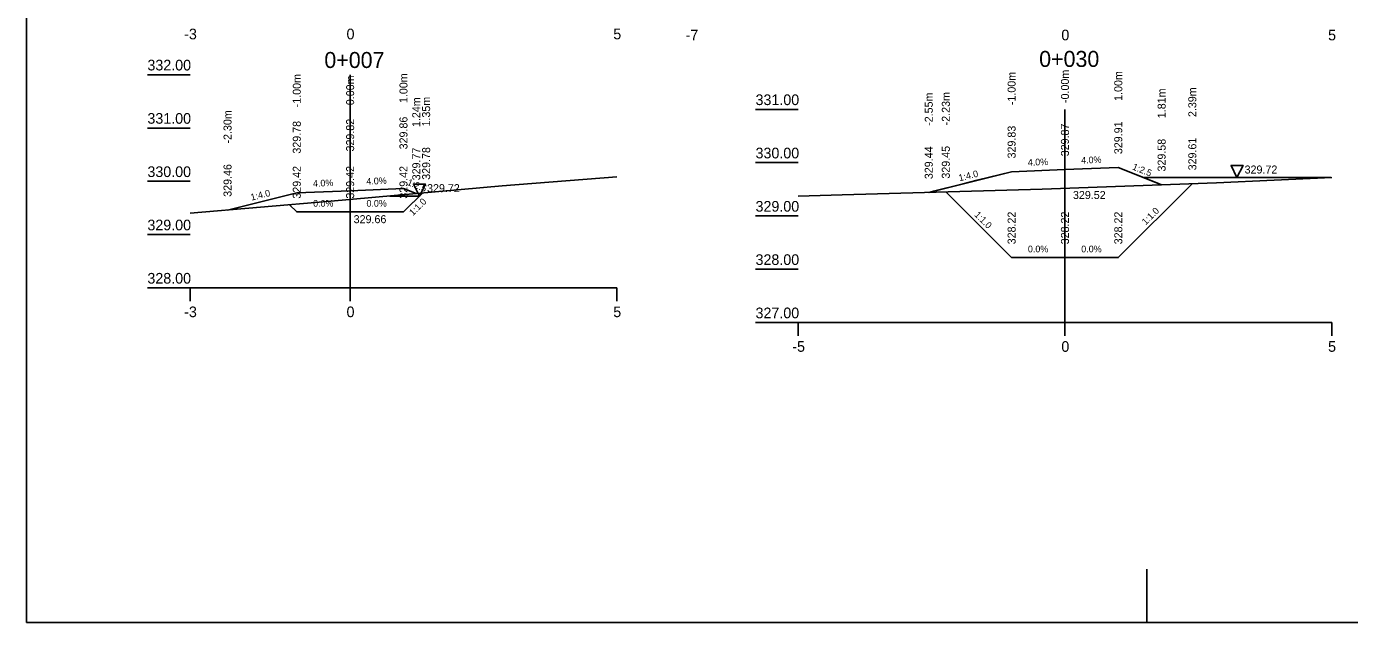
# Model space of a CAD drawing. Extents: x -560266.4 to -560224.4, y -1163068.4 to -1163038.7.
# Drawn here: x -560266.44 to -560241.64, y -1163068.4 to -1163057.22 of the extents above; entities that cross this region are included whole.
import ezdxf

# ---------------------------------------------------------------- set-up
doc = ezdxf.new("R2010")
doc.units = 0
for name, color, linetype in [('16', 7, 'Continuous'), ('21', 7, 'Continuous'), ('28', 7, 'Continuous'), ('59', 7, 'Continuous'), ('Body pricny rez', 7, 'Continuous'), ('Popis pricneho profilu', 7, 'Continuous')]:
    doc.layers.add(name, color=color, linetype=linetype)

msp = doc.modelspace()

# ---------------------------------------------------------------- linework, layer by layer
for p, q in [((-560266.444, -1163038.703), (-560266.444, -1163068.403)), ((-560245.444, -1163068.403), (-560245.444, -1163067.403)), ((-560266.444, -1163068.403), (-560224.444, -1163068.403))]:
    msp.add_line(p, q)
for points in [[(-560243.752, -1163060.049), (-560243.864, -1163059.824), (-560243.639, -1163059.824)], [(-560259.077, -1163060.399), (-560259.19, -1163060.174), (-560258.965, -1163060.174)]]:
    msp.add_lwpolyline(points, close=True)
for points in [[(-560263.377, -1163060.723), (-560260.741, -1163060.498), (-560257.525, -1163060.209), (-560255.377, -1163060.038)], [(-560251.977, -1163060.402), (-560251.153, -1163060.379), (-560247.405, -1163060.27), (-560244.135, -1163060.15), (-560241.977, -1163060.049)], [(-560249.53, -1163060.332), (-560249.44, -1163060.309), (-560248.884, -1163060.17), (-560248.621, -1163060.104), (-560247.977, -1163059.943), (-560246.977, -1163059.903), (-560245.977, -1163059.863), (-560245.254, -1163060.153), (-560245.165, -1163060.188)], [(-560247.977, -1163059.943), (-560249.53, -1163060.332)], [(-560246.977, -1163059.903), (-560247.977, -1163059.943)], [(-560246.977, -1163059.903), (-560245.977, -1163059.863)], [(-560245.977, -1163059.863), (-560245.165, -1163060.188)], [(-560245.512, -1163060.049), (-560241.991, -1163060.049)], [(-560261.377, -1163060.338), (-560262.675, -1163060.663)], [(-560260.377, -1163060.298), (-560261.377, -1163060.338)], [(-560260.377, -1163060.298), (-560259.377, -1163060.258)], [(-560259.377, -1163060.258), (-560259.137, -1163060.354)], [(-560249.21, -1163060.322), (-560247.977, -1163061.555), (-560246.977, -1163061.555), (-560245.977, -1163061.555), (-560244.589, -1163060.167)], [(-560247.977, -1163061.555), (-560249.21, -1163060.322)], [(-560245.977, -1163061.555), (-560244.589, -1163060.167)], [(-560261.512, -1163060.564), (-560261.377, -1163060.698), (-560260.881, -1163060.698), (-560260.377, -1163060.698), (-560259.881, -1163060.698), (-560259.377, -1163060.698), (-560259.355, -1163060.676), (-560259.023, -1163060.344)], [(-560259.63, -1163060.399), (-560259.077, -1163060.399)], [(-560259.377, -1163060.698), (-560259.023, -1163060.344)], [(-560260.377, -1163060.698), (-560261.377, -1163060.698)], [(-560260.377, -1163060.698), (-560259.377, -1163060.698)], [(-560246.977, -1163061.555), (-560247.977, -1163061.555)], [(-560246.977, -1163061.555), (-560245.977, -1163061.555)]]:
    msp.add_lwpolyline(points)
at = {"layer": '16'}
for p, q in [((-560263.377, -1163062.122), (-560255.377, -1163062.122)), ((-560251.977, -1163062.772), (-560241.977, -1163062.772))]:
    msp.add_line(p, q, dxfattribs=at)
at = {"layer": '21'}
for p, q in [((-560264.177, -1163058.122), (-560263.377, -1163058.122)), ((-560252.777, -1163058.772), (-560251.977, -1163058.772)), ((-560264.177, -1163059.122), (-560263.377, -1163059.122)), ((-560252.777, -1163059.772), (-560251.977, -1163059.772)), ((-560264.177, -1163060.122), (-560263.377, -1163060.122)), ((-560252.777, -1163060.772), (-560251.977, -1163060.772)), ((-560264.177, -1163061.122), (-560263.377, -1163061.122)), ((-560252.777, -1163061.772), (-560251.977, -1163061.772)), ((-560264.177, -1163062.122), (-560263.377, -1163062.122)), ((-560252.777, -1163062.772), (-560251.977, -1163062.772))]:
    msp.add_line(p, q, dxfattribs=at)
at = {"layer": '28'}
for p, q in [((-560260.377, -1163058.122), (-560260.377, -1163062.122)), ((-560246.977, -1163058.772), (-560246.977, -1163062.772))]:
    msp.add_line(p, q, dxfattribs=at)
at = {"layer": '59'}
for p, q in [((-560263.377, -1163062.372), (-560263.377, -1163062.122)), ((-560260.377, -1163062.372), (-560260.377, -1163062.122)), ((-560255.377, -1163062.372), (-560255.377, -1163062.122)), ((-560251.977, -1163063.022), (-560251.977, -1163062.772)), ((-560246.977, -1163063.022), (-560246.977, -1163062.772)), ((-560241.977, -1163063.022), (-560241.977, -1163062.772))]:
    msp.add_line(p, q, dxfattribs=at)

# ---------------------------------------------------------------- texts
for s, height, p in [('0+007', 0.3, (-560260.86, -1163057.996)), ('0+030', 0.3, (-560247.46, -1163057.976)), ('329.72', 0.15, (-560243.609, -1163059.976)), ('329.72', 0.15, (-560258.935, -1163060.326))]:
    msp.add_text(s, height=height).set_placement(p)
for s, rotation, p in [('1:2.5', 338.1986, (-560245.725, -1163059.897)), ('1:2.5', 338.1986, (-560259.318, -1163060.188)), ('1:4.0', 14.0362, (-560248.953, -1163060.123)), ('1:4.0', 14.0362, (-560262.225, -1163060.486)), ('1:1.0', 45, (-560259.197, -1163060.778)), ('1:1.0', 315, (-560248.684, -1163060.76)), ('1:1.0', 45, (-560245.462, -1163060.951))]:
    msp.add_text(s, height=0.125, rotation=rotation).set_placement(p)
at = {"layer": '16'}
for s, rotation, p in [('4.0%', 2.2906, (-560247.671, -1163059.831)), ('4.0%', 2.2906, (-560246.671, -1163059.791)), ('4.0%', 2.2906, (-560261.071, -1163060.226)), ('4.0%', 2.2906, (-560260.071, -1163060.186)), ('0.0%', 0, (-560261.071, -1163060.598)), ('0.0%', 0, (-560260.071, -1163060.598))]:
    msp.add_text(s, height=0.125, rotation=rotation, dxfattribs=at).set_placement(p)
for p in [(-560247.671, -1163061.455), (-560246.671, -1163061.455)]:
    msp.add_text('0.0%', height=0.125, dxfattribs=at).set_placement(p)
at = {"layer": '21'}
for s, p in [('-3', (-560263.488, -1163057.458)), ('0', (-560260.444, -1163057.458)), ('5', (-560255.444, -1163057.458)), ('-7', (-560254.088, -1163057.477)), ('0', (-560247.044, -1163057.477)), ('5', (-560242.044, -1163057.477)), ('332.00', (-560264.177, -1163058.042)), ('331.00', (-560252.777, -1163058.692)), ('331.00', (-560264.177, -1163059.042)), ('330.00', (-560252.777, -1163059.692)), ('330.00', (-560264.177, -1163060.042)), ('329.00', (-560252.777, -1163060.692)), ('329.00', (-560264.177, -1163061.042)), ('328.00', (-560252.777, -1163061.692)), ('328.00', (-560264.177, -1163062.042)), ('-3', (-560263.488, -1163062.672)), ('0', (-560260.444, -1163062.672)), ('5', (-560255.444, -1163062.672)), ('327.00', (-560252.777, -1163062.692)), ('-5', (-560252.088, -1163063.322)), ('0', (-560247.044, -1163063.322)), ('5', (-560242.044, -1163063.322))]:
    msp.add_text(s, height=0.2, dxfattribs=at).set_placement(p)
at = {"layer": '59'}
for s, p in [('329.52', (-560246.827, -1163060.454)), ('329.66', (-560260.311, -1163060.908))]:
    msp.add_text(s, height=0.15, dxfattribs=at).set_placement(p)
at = {"layer": 'Body pricny rez'}
for p in [(-560247.978, -1163059.944), (-560246.978, -1163059.904), (-560245.978, -1163059.864), (-560261.378, -1163060.339), (-560260.378, -1163060.299), (-560259.378, -1163060.259), (-560249.531, -1163060.332), (-560249.21, -1163060.323), (-560245.166, -1163060.189), (-560244.589, -1163060.168), (-560259.138, -1163060.355), (-560259.023, -1163060.345), (-560262.675, -1163060.663), (-560261.378, -1163060.699), (-560260.378, -1163060.699), (-560259.378, -1163060.699), (-560247.978, -1163061.556), (-560246.978, -1163061.556), (-560245.978, -1163061.556)]:
    msp.add_text('+', height=0.001, dxfattribs=at).set_placement(p)
at = {"layer": 'Popis pricneho profilu'}
for s, p in [('1.00m', (-560259.302, -1163058.654)), ('-1.00m', (-560247.902, -1163058.693)), ('-0.00m', (-560246.902, -1163058.653)), ('1.00m', (-560245.902, -1163058.613)), ('-1.00m', (-560261.302, -1163058.734)), ('0.00m', (-560260.302, -1163058.694)), ('1.24m', (-560259.062, -1163059.104)), ('1.35m', (-560258.877, -1163059.094)), ('-2.55m', (-560249.455, -1163059.082)), ('-2.23m', (-560249.135, -1163059.072)), ('1.81m', (-560245.09, -1163058.938)), ('2.39m', (-560244.514, -1163058.917)), ('-2.30m', (-560262.6, -1163059.413)), ('329.78', (-560261.302, -1163059.603)), ('329.82', (-560260.302, -1163059.563)), ('329.86', (-560259.302, -1163059.523)), ('329.83', (-560247.902, -1163059.693)), ('329.87', (-560246.902, -1163059.653)), ('329.91', (-560245.902, -1163059.613)), ('329.58', (-560245.09, -1163059.938)), ('329.61', (-560244.514, -1163059.917)), ('329.77', (-560259.062, -1163060.104)), ('329.78', (-560258.877, -1163060.094)), ('329.44', (-560249.455, -1163060.082)), ('329.45', (-560249.135, -1163060.072)), ('329.46', (-560262.6, -1163060.413)), ('329.42', (-560261.302, -1163060.448)), ('329.42', (-560260.302, -1163060.448)), ('329.42', (-560259.302, -1163060.448)), ('328.22', (-560247.902, -1163061.305)), ('328.22', (-560246.902, -1163061.305)), ('328.22', (-560245.902, -1163061.305))]:
    msp.add_text(s, height=0.15, rotation=90, dxfattribs=at).set_placement(p)

doc.saveas('drawing.dxf')
